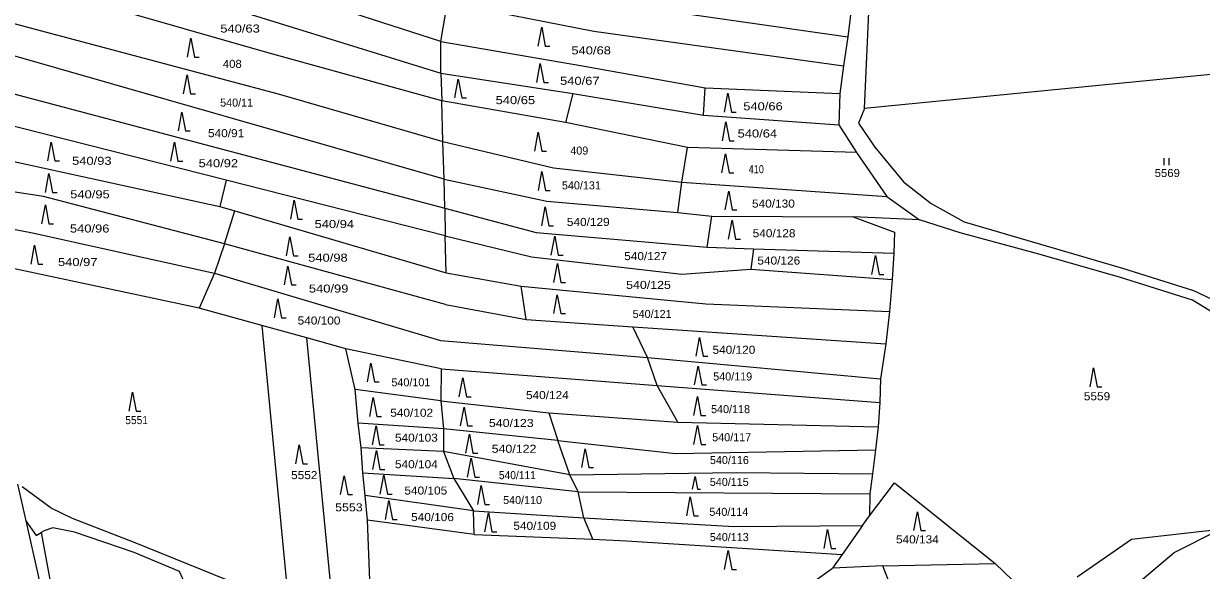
# Model space of a CAD drawing. Extents: x -590528 to -586543, y -1119609 to -1116685.
# Drawn here: x -589803.6 to -589555, y -1118528.6 to -1118413 of the extents above; entities that cross this region are included whole.
import ezdxf
from ezdxf.enums import TextEntityAlignment as Align

# ---------------------------------------------------------------- set-up
doc = ezdxf.new("R2010")
doc.units = 0
doc.header["$LTSCALE"] = 0.68
for name, color, linetype, lineweight in [('1', 7, 'Continuous', 13), ('3', 7, 'Continuous', 13), ('4', 7, 'Continuous', 25), ('6', 7, 'Continuous', 13)]:
    doc.layers.add(name, color=color, linetype=linetype, lineweight=lineweight)

msp = doc.modelspace()

# ---------------------------------------------------------------- linework, layer by layer
at = {"layer": '1'}
for p, q in [((-589715.56, -1118416.83), (-589803.34, -1118388.31)), ((-589626.1, -1118430.96), (-589624.67, -1118398.05)), ((-589776.96, -1118404.44), (-589715.54, -1118423.49)), ((-589681.67, -1118408.35), (-589629.64, -1118415.81)), ((-589628.6, -1118407.69), (-589629.64, -1118415.81)), ((-589683.22, -1118414.58), (-589630.54, -1118421.94)), ((-589629.64, -1118415.81), (-589630.54, -1118421.94)), ((-589714.86, -1118445.85), (-589807.68, -1118419.28)), ((-589685.66, -1118421.94), (-589659.75, -1118426.61)), ((-589542.02, -1118422.69), (-589626.1, -1118430.96)), ((-589715.54, -1118423.49), (-589715.36, -1118429.31)), ((-589715.54, -1118423.49), (-589687.68, -1118427.78)), ((-589811.28, -1118426.37), (-589714.69, -1118451.98)), ((-589687.68, -1118427.78), (-589689.25, -1118433.9)), ((-589687.68, -1118427.78), (-589660.06, -1118432.36)), ((-589660.06, -1118432.36), (-589659.75, -1118426.61)), ((-589659.75, -1118426.61), (-589631.29, -1118427.79)), ((-589760.87, -1118446.11), (-589813.61, -1118432.73)), ((-589660.06, -1118432.36), (-589631.55, -1118434.41)), ((-589631.55, -1118434.41), (-589627.8, -1118440.25)), ((-589715.14, -1118437.94), (-589691.75, -1118443.46)), ((-589627.8, -1118440.25), (-589621.36, -1118449.55)), ((-589799.4, -1118449.52), (-589819.12, -1118446.65)), ((-589760.87, -1118446.11), (-589762.17, -1118451.67)), ((-589714.86, -1118445.85), (-589693.19, -1118450.53)), ((-589665.5, -1118452.96), (-589664.68, -1118446.51)), ((-589664.68, -1118446.51), (-589621.36, -1118449.55)), ((-589761.21, -1118459.53), (-589799.4, -1118449.52)), ((-589761.21, -1118459.53), (-589759.02, -1118452.58)), ((-589714.69, -1118451.98), (-589714.66, -1118457.84)), ((-589714.69, -1118451.98), (-589695.39, -1118457.14)), ((-589714.66, -1118457.84), (-589696.43, -1118462.28)), ((-589761.21, -1118459.53), (-589763.31, -1118465.77)), ((-589714.58, -1118472.34), (-589761.21, -1118459.53)), ((-589649.53, -1118460.61), (-589619.9, -1118461.5)), ((-589766.58, -1118473.15), (-589805.53, -1118464.81)), ((-589650.1, -1118464.9), (-589620.28, -1118467.07)), ((-589763.31, -1118465.77), (-589715.59, -1118479.98)), ((-589714.43, -1118465.7), (-589698.55, -1118468.47)), ((-589697.55, -1118475.54), (-589698.55, -1118468.47)), ((-589698.55, -1118468.47), (-589659.59, -1118472.19)), ((-589714.58, -1118472.34), (-589697.55, -1118475.54)), ((-589659.59, -1118472.19), (-589620.84, -1118473.83)), ((-589753.37, -1118476.81), (-589766.58, -1118473.15)), ((-589753.37, -1118476.81), (-589747.62, -1118536.12)), ((-589697.55, -1118475.54), (-589675.03, -1118477.06)), ((-589675.03, -1118477.06), (-589621.63, -1118480.69)), ((-589735.59, -1118481.73), (-589743.85, -1118479.44)), ((-589715.59, -1118479.98), (-589671.94, -1118483.54)), ((-589715.49, -1118485.99), (-589735.59, -1118481.73)), ((-589733.66, -1118490.31), (-589735.59, -1118481.73)), ((-589671.94, -1118483.54), (-589622.7, -1118488.04)), ((-589715.49, -1118485.99), (-589669.86, -1118489.45)), ((-589715.57, -1118492.75), (-589733.66, -1118490.31)), ((-589733.01, -1118497.45), (-589733.66, -1118490.31)), ((-589669.86, -1118489.45), (-589622.87, -1118493.07)), ((-589692.71, -1118495.22), (-589665.49, -1118497.25)), ((-589715.01, -1118498.6), (-589733.01, -1118497.45)), ((-589732.36, -1118502.67), (-589733.01, -1118497.45)), ((-589665.49, -1118497.25), (-589623.2, -1118498.24)), ((-589690.83, -1118501.09), (-589715.01, -1118498.6)), ((-589714.95, -1118503.42), (-589732.36, -1118502.67)), ((-589732.01, -1118507.92), (-589732.36, -1118502.67)), ((-589690.83, -1118501.09), (-589666.01, -1118503.84)), ((-589688.32, -1118508.37), (-589714.95, -1118503.42)), ((-589666.01, -1118503.84), (-589623.75, -1118503.06)), ((-589732.01, -1118507.92), (-589712.81, -1118509.13)), ((-589731.49, -1118512.75), (-589732.01, -1118507.92)), ((-589686.56, -1118511.94), (-589712.81, -1118509.13)), ((-589688.32, -1118508.37), (-589653.19, -1118507.89)), ((-589653.19, -1118507.89), (-589624.43, -1118508.11)), ((-589708.66, -1118515.99), (-589731.49, -1118512.75)), ((-589731, -1118517.92), (-589731.49, -1118512.75)), ((-589686.56, -1118511.94), (-589624.99, -1118512.36)), ((-589685.37, -1118517.42), (-589686.56, -1118511.94)), ((-589624.99, -1118512.36), (-589625.07, -1118517.01)), ((-589708.66, -1118515.99), (-589685.37, -1118517.42)), ((-589708.52, -1118520.99), (-589708.66, -1118515.99)), ((-589626.5, -1118519.03), (-589625.07, -1118517.01)), ((-589708.52, -1118520.99), (-589731, -1118517.92)), ((-589730.5, -1118530.64), (-589731, -1118517.92)), ((-589626.5, -1118519.03), (-589630.84, -1118525.17)), ((-589708.52, -1118520.99), (-589683.48, -1118521.94)), ((-589683.48, -1118521.94), (-589676.36, -1118522.31)), ((-589622.26, -1118527.58), (-589632.84, -1118528.07)), ((-589622.26, -1118527.58), (-589598.49, -1118527.11)), ((-589598.49, -1118527.11), (-589589.78, -1118535.43)), ((-589642.92, -1118535.24), (-589632.84, -1118528.07))]:
    msp.add_line(p, q, dxfattribs=at)
for points in [[(-589752.3, -1118419.13), (-589804.65, -1118404.07), (-589806.52, -1118403.53), (-589808.35, -1118412.31), (-589806.46, -1118412.81), (-589749.91, -1118427.87)], [(-589715.56, -1118416.83), (-589714.12, -1118408.57), (-589683.22, -1118414.58)], [(-589715.54, -1118423.49), (-589715.56, -1118416.83), (-589685.66, -1118421.94)], [(-589689.25, -1118433.9), (-589715.36, -1118429.31), (-589752.3, -1118419.13)], [(-589630.54, -1118421.94), (-589631.29, -1118427.79), (-589631.55, -1118434.41)], [(-589749.91, -1118427.87), (-589715.14, -1118437.94), (-589715.36, -1118429.31)], [(-589626.1, -1118430.96), (-589627.36, -1118434.04), (-589623.95, -1118439.1), (-589617.85, -1118446.45), (-589612.06, -1118450.99), (-589605.04, -1118454.87), (-589571.63, -1118464.71), (-589556.61, -1118469.42), (-589543.84, -1118475.46), (-589529.99, -1118483.72), (-589518.8, -1118483.93), (-589514.46, -1118427.18)], [(-589627.8, -1118440.25), (-589663.44, -1118439.17), (-589689.25, -1118433.9)], [(-589714.69, -1118451.98), (-589714.86, -1118445.85), (-589715.14, -1118437.94)], [(-589816.41, -1118439.82), (-589762.17, -1118451.67), (-589759.02, -1118452.58)], [(-589691.75, -1118443.46), (-589664.68, -1118446.51), (-589663.44, -1118439.17)], [(-589759.02, -1118452.58), (-589714.43, -1118465.7), (-589714.66, -1118457.84), (-589760.87, -1118446.11)], [(-589693.19, -1118450.53), (-589665.5, -1118452.96), (-589658.36, -1118453.68), (-589628.51, -1118453.85)], [(-589621.36, -1118449.55), (-589614.46, -1118454.46), (-589628.51, -1118453.85), (-589619.74, -1118457.1), (-589619.9, -1118461.5), (-589620.28, -1118467.07), (-589620.84, -1118473.83), (-589621.63, -1118480.69)], [(-589821.8, -1118453.36), (-589801.75, -1118457.22), (-589763.31, -1118465.77), (-589766.58, -1118473.15)], [(-589695.39, -1118457.14), (-589659.32, -1118460.23), (-589658.36, -1118453.68)], [(-589589.8, -1118461.61), (-589605.87, -1118457.22), (-589614.46, -1118454.46)], [(-589659.32, -1118460.23), (-589649.53, -1118460.61), (-589650.1, -1118464.9)], [(-589696.43, -1118462.28), (-589664.67, -1118465.95), (-589650.1, -1118464.9)], [(-589535.79, -1118484.33), (-589556.88, -1118471.45), (-589572.23, -1118466.61), (-589589.8, -1118461.61)], [(-589737.86, -1118541.33), (-589743.85, -1118479.44), (-589753.37, -1118476.81)], [(-589665.49, -1118497.25), (-589669.86, -1118489.45), (-589671.94, -1118483.54), (-589675.03, -1118477.06)], [(-589621.63, -1118480.69), (-589622.7, -1118488.04), (-589622.87, -1118493.07), (-589623.2, -1118498.24), (-589623.75, -1118503.06), (-589624.43, -1118508.11), (-589624.99, -1118512.36)], [(-589715.49, -1118485.99), (-589715.57, -1118492.75), (-589715.01, -1118498.6), (-589714.95, -1118503.42), (-589712.81, -1118509.13), (-589708.66, -1118515.99)], [(-589715.57, -1118492.75), (-589692.71, -1118495.22), (-589690.83, -1118501.09)], [(-589686.56, -1118511.94), (-589688.32, -1118508.37), (-589690.83, -1118501.09)], [(-589625.07, -1118517.01), (-589619.78, -1118510.03), (-589598.49, -1118527.11)], [(-589752.29, -1118533.93), (-589760.79, -1118530.55), (-589780.1, -1118522.71), (-589793.32, -1118517.55), (-589797.82, -1118515.43), (-589803.94, -1118510.86)], [(-589683.48, -1118521.94), (-589685.37, -1118517.42), (-589653.65, -1118519.27), (-589626.5, -1118519.03)], [(-589803.18, -1118518.05), (-589800.96, -1118521.15), (-589799.92, -1118520.53)], [(-589736.51, -1118603.8), (-589770.72, -1118528.79), (-589780.32, -1118524.78), (-589792.91, -1118520.44), (-589797.44, -1118519.57), (-589799.31, -1118520.17), (-589799.92, -1118520.53), (-589793.31, -1118556.48), (-589792.02, -1118562.86), (-589790.56, -1118569.1), (-589785.03, -1118590.87), (-589783.85, -1118595.99), (-589782.82, -1118601.16), (-589781.93, -1118606.34)], [(-589536.6, -1118606.53), (-589558.87, -1118559.4), (-589570.68, -1118533.18), (-589560.7, -1118524.73), (-589551.05, -1118519.91), (-589569.71, -1118522), (-589581.21, -1118530.01)], [(-589676.36, -1118522.31), (-589630.84, -1118525.17), (-589632.84, -1118528.07)], [(-589604.33, -1118537.13), (-589610.8, -1118557.16), (-589622.26, -1118527.58)]]:
    msp.add_lwpolyline(points, dxfattribs=at)
at = {"layer": '4'}
msp.add_line((-589804.92, -1118510.3), (-589803.18, -1118518.05), dxfattribs=at)
msp.add_lwpolyline([(-589803.18, -1118518.05), (-589800.58, -1118529.65), (-589795.58, -1118558.28)], dxfattribs=at)
at = {"layer": '6'}
for p, q in [((-589562.81, -1118442.94), (-589562.81, -1118441.44)), ((-589561.81, -1118442.94), (-589561.81, -1118441.44))]:
    msp.add_line(p, q, dxfattribs=at)
for points in [[(-589695, -1118417.76), (-589694.25, -1118413.76), (-589693.5, -1118417.76), (-589692.5, -1118417.76)], [(-589769.06, -1118420.12), (-589768.31, -1118416.12), (-589767.56, -1118420.12), (-589766.56, -1118420.12)], [(-589695.29, -1118425.44), (-589694.54, -1118421.44), (-589693.79, -1118425.44), (-589692.79, -1118425.44)], [(-589769.86, -1118427.86), (-589769.11, -1118423.86), (-589768.36, -1118427.86), (-589767.36, -1118427.86)], [(-589712.61, -1118428.72), (-589711.86, -1118424.72), (-589711.11, -1118428.72), (-589710.11, -1118428.72)], [(-589655.69, -1118431.74), (-589654.94, -1118427.74), (-589654.19, -1118431.74), (-589653.19, -1118431.74)], [(-589770.96, -1118435.7), (-589770.21, -1118431.7), (-589769.46, -1118435.7), (-589768.46, -1118435.7)], [(-589656.1, -1118437.75), (-589655.35, -1118433.75), (-589654.6, -1118437.75), (-589653.6, -1118437.75)], [(-589798.55, -1118442.04), (-589797.8, -1118438.04), (-589797.05, -1118442.04), (-589796.05, -1118442.04)], [(-589772.54, -1118442.08), (-589771.79, -1118438.08), (-589771.04, -1118442.08), (-589770.04, -1118442.08)], [(-589695.72, -1118439.96), (-589694.97, -1118435.96), (-589694.22, -1118439.96), (-589693.22, -1118439.96)], [(-589656.19, -1118444.54), (-589655.44, -1118440.54), (-589654.69, -1118444.54), (-589653.69, -1118444.54)], [(-589799.03, -1118448.67), (-589798.28, -1118444.67), (-589797.53, -1118448.67), (-589796.53, -1118448.67)], [(-589694.94, -1118448.25), (-589694.19, -1118444.25), (-589693.44, -1118448.25), (-589692.44, -1118448.25)], [(-589747.23, -1118454.33), (-589746.48, -1118450.33), (-589745.73, -1118454.33), (-589744.73, -1118454.33)], [(-589655.52, -1118452.39), (-589654.77, -1118448.39), (-589654.02, -1118452.39), (-589653.02, -1118452.39)], [(-589799.79, -1118455.31), (-589799.04, -1118451.31), (-589798.29, -1118455.31), (-589797.29, -1118455.31)], [(-589694.24, -1118455.74), (-589693.49, -1118451.74), (-589692.74, -1118455.74), (-589691.74, -1118455.74)], [(-589654.81, -1118458.57), (-589654.06, -1118454.57), (-589653.31, -1118458.57), (-589652.31, -1118458.57)], [(-589748.16, -1118462.06), (-589747.41, -1118458.06), (-589746.66, -1118462.06), (-589745.66, -1118462.06)], [(-589692.24, -1118461.96), (-589691.49, -1118457.96), (-589690.74, -1118461.96), (-589689.74, -1118461.96)], [(-589802.05, -1118463.83), (-589801.3, -1118459.83), (-589800.55, -1118463.83), (-589799.55, -1118463.83)], [(-589624.53, -1118466.04), (-589623.78, -1118462.04), (-589623.03, -1118466.04), (-589622.03, -1118466.04)], [(-589748.58, -1118468.24), (-589747.83, -1118464.24), (-589747.08, -1118468.24), (-589746.08, -1118468.24)], [(-589691.69, -1118467.73), (-589690.94, -1118463.73), (-589690.19, -1118467.73), (-589689.19, -1118467.73)], [(-589691.71, -1118474.29), (-589690.96, -1118470.29), (-589690.21, -1118474.29), (-589689.21, -1118474.29)], [(-589750.69, -1118475.17), (-589749.94, -1118471.17), (-589749.19, -1118475.17), (-589748.19, -1118475.17)], [(-589661.66, -1118483.31), (-589660.91, -1118479.31), (-589660.16, -1118483.31), (-589659.16, -1118483.31)], [(-589731.05, -1118488.73), (-589730.3, -1118484.73), (-589729.55, -1118488.73), (-589728.55, -1118488.73)], [(-589661.96, -1118489.37), (-589661.21, -1118485.37), (-589660.46, -1118489.37), (-589659.46, -1118489.37)], [(-589711.65, -1118491.86), (-589710.9, -1118487.86), (-589710.15, -1118491.86), (-589709.15, -1118491.86)], [(-589578.49, -1118489.76), (-589577.74, -1118485.76), (-589576.99, -1118489.76), (-589575.99, -1118489.76)], [(-589781.37, -1118494.88), (-589780.62, -1118490.88), (-589779.87, -1118494.88), (-589778.87, -1118494.88)], [(-589730.55, -1118496), (-589729.8, -1118492), (-589729.05, -1118496), (-589728.05, -1118496)], [(-589662.13, -1118495.81), (-589661.38, -1118491.81), (-589660.63, -1118495.81), (-589659.63, -1118495.81)], [(-589711.38, -1118498.03), (-589710.63, -1118494.03), (-589709.88, -1118498.03), (-589708.88, -1118498.03)], [(-589729.98, -1118502.02), (-589729.23, -1118498.02), (-589728.48, -1118502.02), (-589727.48, -1118502.02)], [(-589710.26, -1118503.78), (-589709.51, -1118499.78), (-589708.76, -1118503.78), (-589707.76, -1118503.78)], [(-589662.1, -1118501.95), (-589661.35, -1118497.95), (-589660.6, -1118501.95), (-589659.6, -1118501.95)], [(-589746.19, -1118506), (-589745.44, -1118502), (-589744.69, -1118506), (-589743.69, -1118506)], [(-589685.79, -1118506.84), (-589685.04, -1118502.84), (-589684.29, -1118506.84), (-589683.29, -1118506.84)], [(-589729.89, -1118507.22), (-589729.14, -1118503.22), (-589728.39, -1118507.22), (-589727.39, -1118507.22)], [(-589709.89, -1118508.86), (-589709.14, -1118504.86), (-589708.39, -1118508.86), (-589707.39, -1118508.86)], [(-589736.7, -1118512.54), (-589735.95, -1118508.54), (-589735.2, -1118512.54), (-589734.2, -1118512.54)], [(-589728.32, -1118512.44), (-589727.57, -1118508.44), (-589726.82, -1118512.44), (-589725.82, -1118512.44)], [(-589662.382, -1118511.36), (-589661.88, -1118508.68), (-589661.378, -1118511.36), (-589660.708, -1118511.36)], [(-589707.75, -1118514.59), (-589707, -1118510.59), (-589706.25, -1118514.59), (-589705.25, -1118514.59)], [(-589727.24, -1118517.8), (-589726.49, -1118513.8), (-589725.74, -1118517.8), (-589724.74, -1118517.8)], [(-589663.64, -1118516.99), (-589662.89, -1118512.99), (-589662.14, -1118516.99), (-589661.14, -1118516.99)], [(-589706.25, -1118520.4), (-589705.5, -1118516.4), (-589704.75, -1118520.4), (-589703.75, -1118520.4)], [(-589615.69, -1118520.14), (-589614.94, -1118516.14), (-589614.19, -1118520.14), (-589613.19, -1118520.14)], [(-589634.64, -1118523.93), (-589633.89, -1118519.93), (-589633.14, -1118523.93), (-589632.14, -1118523.93)], [(-589655.64, -1118528.33), (-589654.89, -1118524.33), (-589654.14, -1118528.33), (-589653.14, -1118528.33)]]:
    msp.add_lwpolyline(points, dxfattribs=at)

# ---------------------------------------------------------------- texts
at = {"layer": '3'}
for s, width, p in [('540/63', 1.2, (-589757.93, -1118414.91)), ('540/68', 1.2, (-589683.81, -1118419.52)), ('408', 1.05, (-589759.57, -1118422.37)), ('540/67', 1.2, (-589686.2005, -1118425.95)), ('540/65', 1.2, (-589699.8105, -1118430.03)), ('540/66', 1.2, (-589647.53, -1118431.33)), ('540/91', 1.1, (-589760.88, -1118437.01)), ('540/64', 1.2, (-589648.72, -1118437.08)), ('540/93', 1.2, (-589789.23, -1118442.85)), ('540/92', 1.2, (-589762.5105, -1118443.36)), ('410', 0.85, (-589648.9505, -1118444.62)), ('540/95', 1.2, (-589789.6205, -1118449.93)), ('540/130', 1.1, (-589645.33, -1118451.89)), ('540/96', 1.2, (-589789.68, -1118457.16)), ('540/94', 1.2, (-589738.03, -1118456.21)), ('540/129', 1.1, (-589684.4205, -1118455.77)), ('540/128', 1.1, (-589645.19, -1118458.15)), ('540/97', 1.2, (-589792.2005, -1118464.25)), ('540/98', 1.2, (-589739.38, -1118463.32)), ('540/127', 1.1, (-589672.3105, -1118462.99)), ('540/126', 1.1, (-589644.2005, -1118463.93)), ('540/125', 1.15, (-589671.7005, -1118469.08)), ('540/99', 1.2, (-589739.23, -1118469.84)), ('540/100', 1.1, (-589741.2605, -1118476.6)), ('540/120', 1.1, (-589653.6705, -1118482.78)), ('540/124', 1.1, (-589693.0505, -1118492.35)), ('540/102', 1.1, (-589721.7005, -1118496.08)), ('540/123', 1.15, (-589700.67, -1118498.25)), ('540/103', 1.1, (-589720.71, -1118501.35)), ('540/122', 1.15, (-589700.0905, -1118503.7)), ('540/104', 1.1, (-589720.71, -1118506.96)), ('540/111', 0.95, (-589699.39, -1118509.27)), ('540/105', 1.1, (-589718.7205, -1118512.52)), ('540/106', 1.1, (-589717.3, -1118518.13)), ('540/109', 1.1, (-589695.71, -1118519.97)), ('540/134', 1.1, (-589614.94, -1118522.84))]:
    msp.add_text(s, height=1.7, dxfattribs=dict(at, width=width)).set_placement(p, align=Align.CENTER)
for s, p in [('540/11', (-589758.6605, -1118430.55)), ('409', (-589686.3205, -1118440.69)), ('540/131', (-589685.87, -1118448.04)), ('540/121', (-589670.9405, -1118475.21)), ('540/101', (-589721.87, -1118489.66)), ('540/119', (-589653.93, -1118488.42)), ('540/118', (-589654.3795, -1118495.32)), ('540/117', (-589654.14, -1118501.26)), ('540/116', (-589654.62, -1118506.08)), ('540/115', (-589654.65, -1118510.7)), ('540/110', (-589698.29, -1118514.53)), ('540/114', (-589654.74, -1118517.02)), ('540/113', (-589654.65, -1118522.36))]:
    msp.add_text(s, height=1.7, dxfattribs=at).set_placement(p, align=Align.CENTER)
for s, width, p in [('5569', 1.05, (-589564.833, -1118445.43)), ('5559', 1.1, (-589579.793, -1118492.6)), ('5551', 0.95, (-589782.173, -1118497.64)), ('5552', 1.1, (-589747.163, -1118509.26)), ('5553', 1.15, (-589737.863, -1118516.07))]:
    msp.add_text(s, height=1.7, dxfattribs=dict(at, width=width)).set_placement(p)

doc.saveas('drawing.dxf')
